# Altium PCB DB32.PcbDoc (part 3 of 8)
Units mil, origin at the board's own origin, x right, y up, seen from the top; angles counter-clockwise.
Board outline 3236.22 x 4456.69 mil, 8 copper layers (Top Layer, MidLayer1, MidLayer2, GND-Layer5, MidLayer3, VCC, MidLayer4, Bottom Layer), stack 61.8 mil thick; 207 components, 474 nets, 1777 pads, 1474 vias.
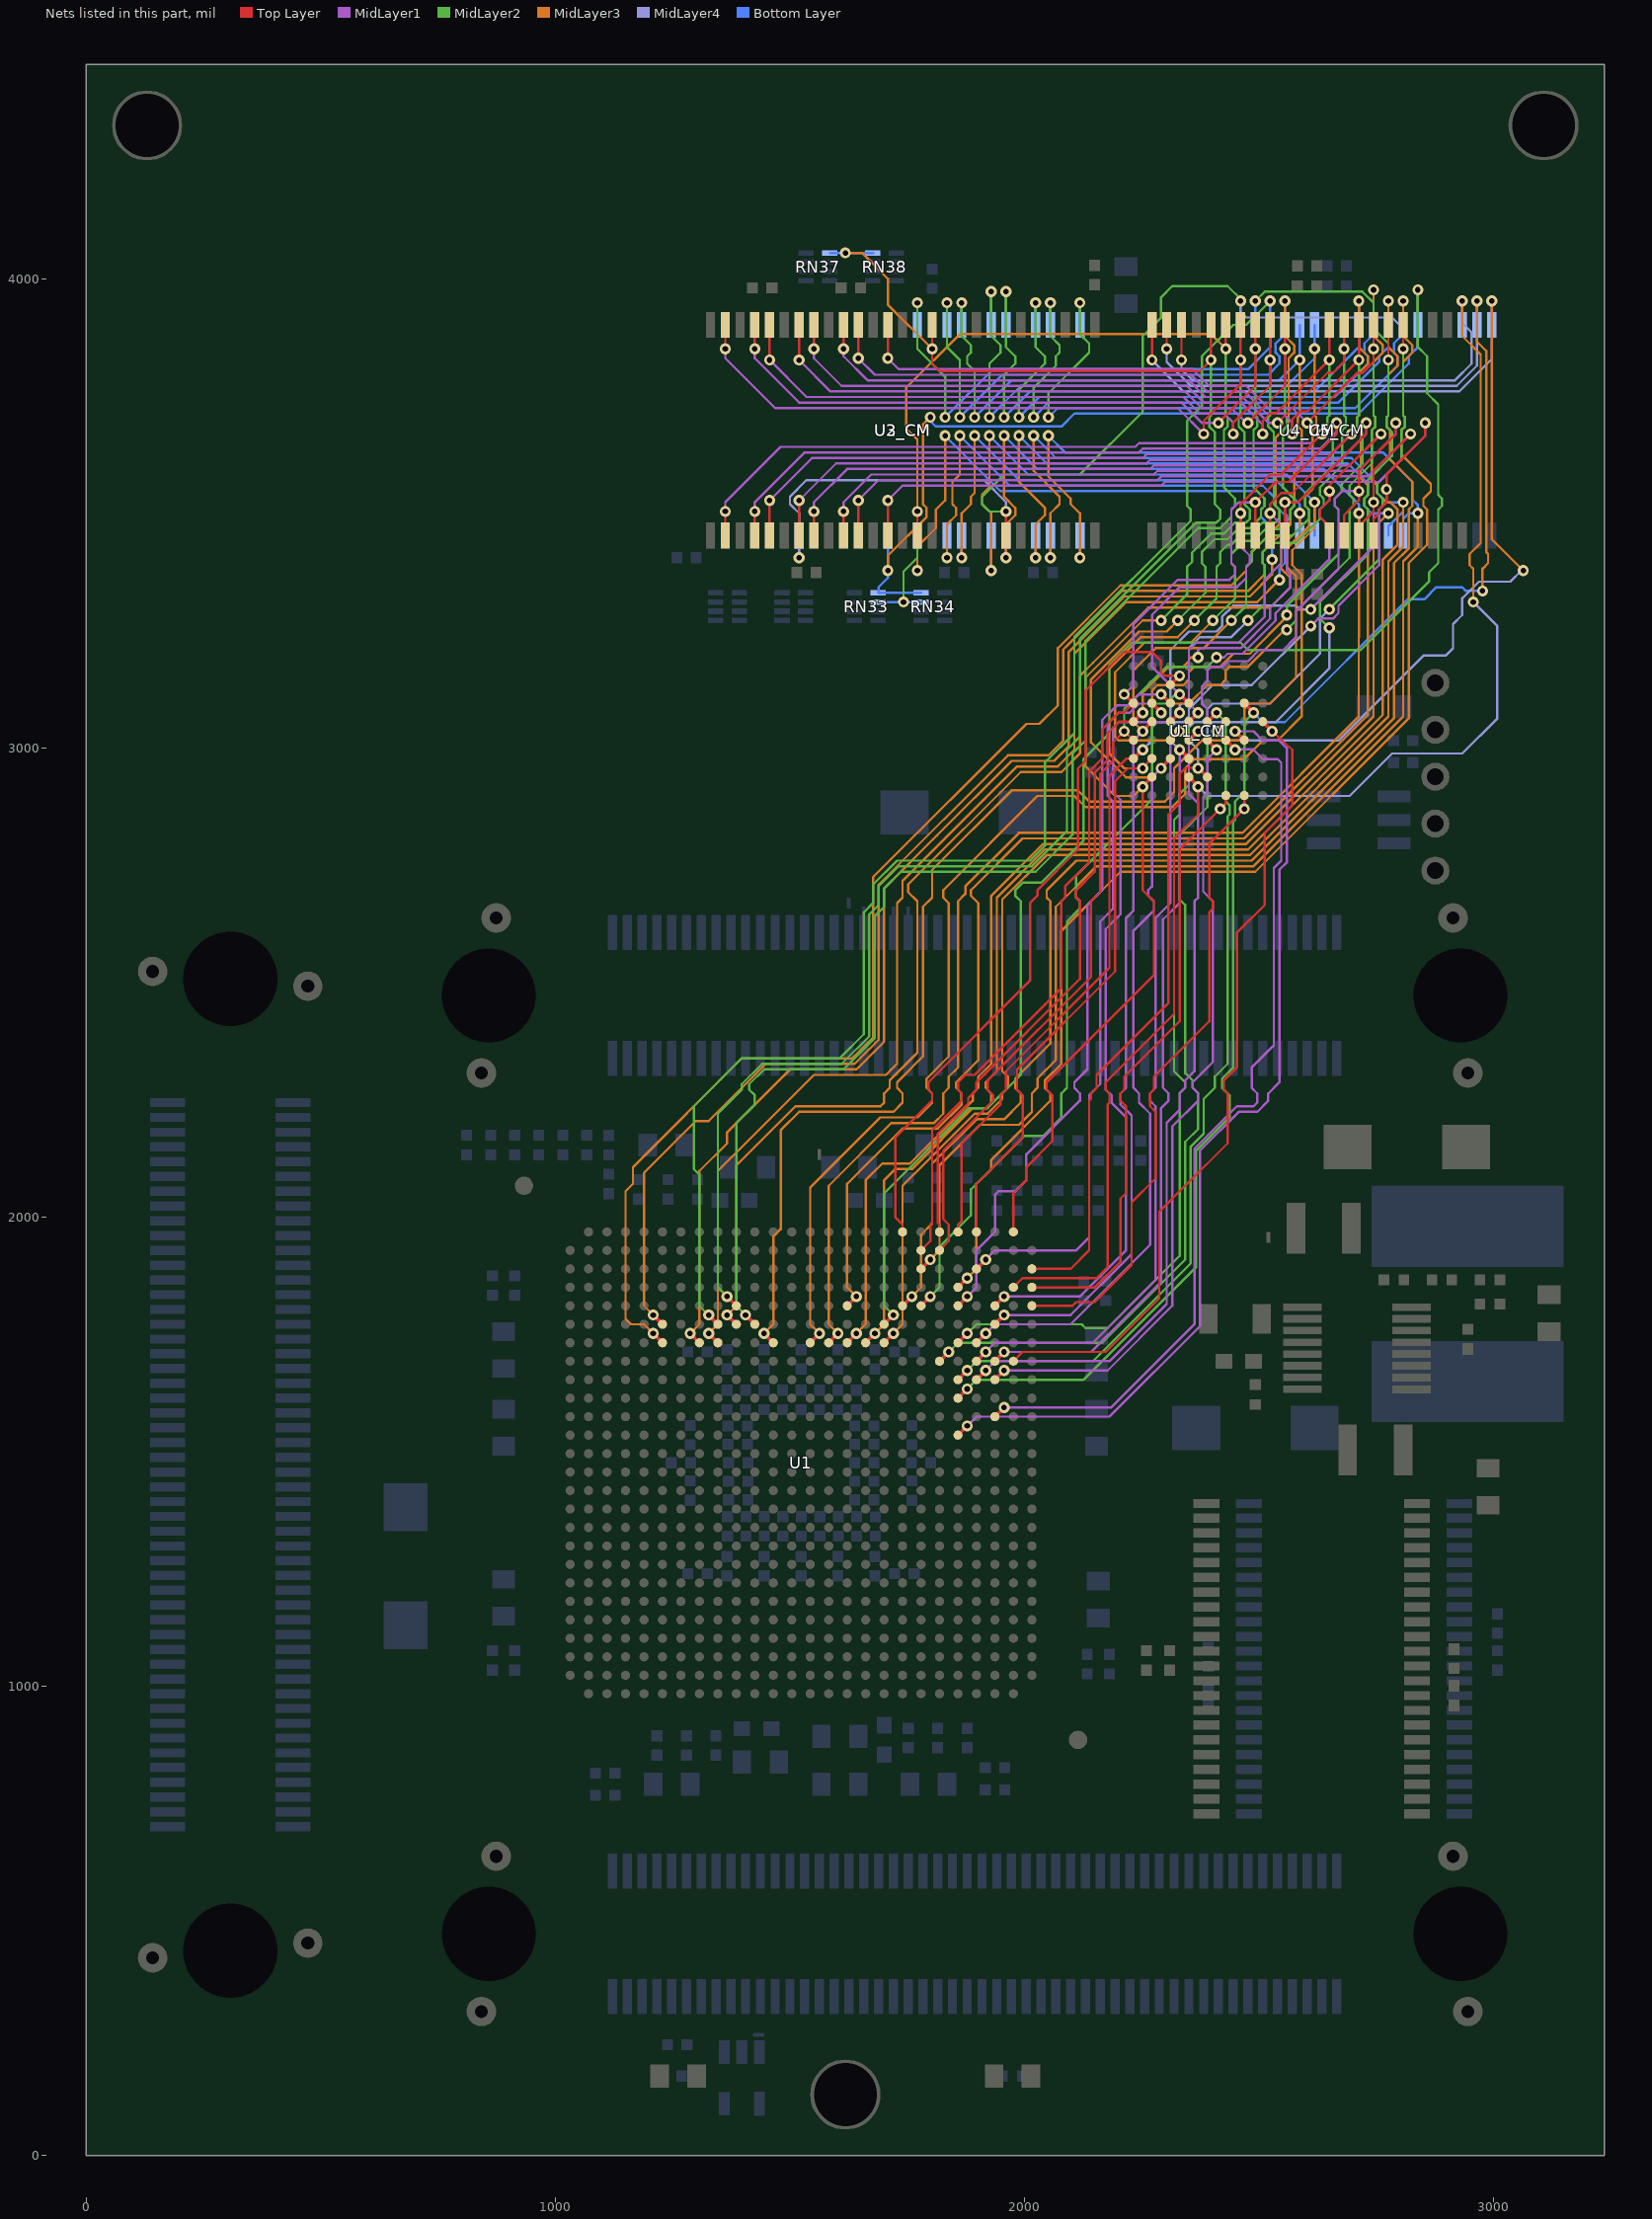
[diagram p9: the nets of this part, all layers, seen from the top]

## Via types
v1: diameter 23.62, hole 11.81, Top Layer to Bottom Layer, 839 vias
v2: diameter 23.62, hole 11.81, Top Layer to Bottom Layer, tented both sides, 499 vias
v3: diameter 27.56, hole 15.75, Top Layer to Bottom Layer, 135 vias
v4: diameter 23.62, hole 11.81, Top Layer to Bottom Layer, tented top, 1 vias

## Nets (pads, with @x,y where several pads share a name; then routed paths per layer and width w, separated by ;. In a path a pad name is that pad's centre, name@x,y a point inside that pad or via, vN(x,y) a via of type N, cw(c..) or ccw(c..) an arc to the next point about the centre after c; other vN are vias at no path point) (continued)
BUS_A16: U1.C26 U1_CM.D7 U2_CM.21 U3_CM.21 U4_CM.27 U5_CM.27 | length 4718.6
  Top Layer w5: U2_CM.21@1960.63,3452.76 v2(1960.63,3503.93) ; U1.C26@2015.75,1889.76 2078.74,1889.76 2090.55,1889.76 2098.43,1889.76 2137.8,1929.13 2137.8,2248.03 2141.73,2251.97 2141.73,2263.78 2153.54,2275.59 2153.54,2303.15 2307.09,2456.69 2307.09,2858.27 2330.71,2881.89 2330.71,2944.88 2343.51,2957.68 v1@2370.08,2957.68 ; v2(2807.09,3850.39) U4_CM.27@2807.09,3901.57
  Top Layer w7.87: v1@2370.08,2957.68 2370.57,2957.19 U1_CM.D7@2389.76,2937.99
  MidLayer2 w5: v2(1960.63,3503.93) 1925.2,3503.93 1909.45,3519.68 1909.45,3535.43 1925.2,3551.18 1956.69,3582.68 2118.11,3582.68 2251.97,3716.54 2251.97,3877.95 2291.34,3917.32 2291.34,3960.63 2314.96,3984.25 2433.07,3984.25 2460.63,3956.69 v2(2460.63,3952.76) ; v1(2649.61,3295.28) 2755.91,3401.57 2755.91,3507.87 2763.78,3515.75 2763.78,3531.5 2751.97,3543.31 2751.97,3562.99 2803.15,3614.17 2803.15,3677.17 2811.02,3685.04 2811.02,3704.72 2807.09,3708.66 v2(2807.09,3850.39)
  MidLayer4 w5: v2(1519.68,3405.51) 1519.68,3500 1500,3519.68 1500,3535.43 1535.43,3570.87 1913.38,3570.87 1960.63,3523.63 v2(1960.63,3503.93) ; v1(2370.08,2956.69) 2370.08,2996.06 2350.39,3015.75 2350.39,3043.31 2362.2,3055.12 2377.95,3055.12 2389.76,3066.93 2389.76,3082.68 2401.57,3094.49 2523.62,3094.49 2629.92,3200.79 2629.92,3275.59 v1(2649.61,3295.28) ; v2(2460.63,3952.76) 2460.63,3929.13 2472.44,3917.32 2783.46,3917.32 2807.09,3893.7 v2(2807.09,3850.39)
  Bottom Layer w5: v2(1519.68,3405.51) U3_CM.21@1519.68,3452.76 ; U5_CM.27@2460.63,3901.57 v2(2460.63,3952.76)
BUS_A17: U1.D25 U1_CM.E7 U4_CM.42 U5_CM.42 | length 3942.3
  Top Layer w5: U1.D25@1976.38,1850.39 1996.06,1870.08 2078.74,1870.08 2090.55,1870.08 2153.54,1870.08 2177.17,1893.7 2177.17,2240.16 2181.1,2244.09 2181.1,2263.78 2173.23,2271.65 2173.23,2287.4 2318.9,2433.07 2318.9,2807.09 2370.08,2858.27 v1(2370.08,2917.32) ; v2(2334.64,3826.77) U4_CM.42@2334.64,3901.57
  Top Layer w7.87: U1_CM.E7@2350.39,2937.99 v1(2370.08,2917.32)
  MidLayer3 w5: v2(2933.07,3952.76) 2933.07,3877.95 2972.44,3838.58 2972.44,3437.01 2948.82,3413.39 2948.82,3389.76 2956.69,3381.89 v1(2956.69,3311.02)
  MidLayer4 w5: v2(2334.64,3826.77) 2334.64,3807.09 2358.27,3783.46 2917.32,3783.46 2952.76,3818.9 2952.76,3885.83 2933.07,3905.51 v2(2933.07,3952.76) ; v1(2370.08,2917.32) 2389.76,2897.64 2692.91,2897.64 2783.46,2988.19 2933.07,2988.19 3007.87,3062.99 3007.87,3259.84 v1(2956.69,3311.02)
  Bottom Layer w5: U5_CM.42@2933.07,3901.57 v2(2933.07,3952.76)
BUS_A18: U1.K22 U1_CM.B3 U4_CM.43 U5_CM.43 | length 4116.9
  Top Layer w5: v2(2303.15,3850.39) U4_CM.43@2303.15,3901.57 ; v1(2488.19,3074.8) v1@2488.19,3075.79
  Top Layer w7.87: U1.K22@1858.27,1614.17 v1(1877.96,1633.86) ; U1_CM.B3@2468.5,3095.47 v1@2488.19,3075.79
  MidLayer2 w5: v1(1877.96,1633.86) 1897.64,1653.54 2078.74,1653.54 2090.55,1653.54 2125.98,1653.54 2366.14,1893.7 2366.14,2141.73 2437.01,2212.6 2437.01,2259.84 2421.26,2275.59 2421.26,2295.28 2444.88,2318.9 2444.88,2673.23 2444.88,2842.52 2448.82,2846.46 2448.82,2885.83 2468.5,2905.51 2468.5,2976.38 2468.5,3055.12 v1(2488.19,3074.8)
  MidLayer3 w5: v2(2964.57,3952.76) 2964.57,3866.14 2984.25,3846.46 2984.25,3417.32 2988.19,3413.39 2988.19,3393.7 2976.38,3381.89 v1(2976.38,3334.65)
  MidLayer4 w5: v2(2303.15,3850.39) 2303.15,3822.83 2354.33,3771.65 2921.26,3771.65 2964.57,3814.96 v2(2964.57,3952.76)
  Bottom Layer w5: v1(2488.19,3074.8) 2507.87,3055.12 2555.12,3055.12 2816.68,3316.68 2852.11,3316.68 2877.95,3342.52 2933.07,3342.52 2940.94,3334.65 v1(2976.38,3334.65) ; U5_CM.43@2964.57,3901.57 v2(2964.57,3952.76)
BUS_A19: U1.H21 U1_CM.C4 U4_CM.44 U5_CM.44 | length 4323.6
  Top Layer w5: v2(2271.65,3826.77) U4_CM.44@2271.65,3901.57
  Top Layer w7.87: U1.H21@1818.9,1692.91 v1(1838.59,1712.6) ; v1(2409.45,3035.43) U1_CM.C4@2429.13,3056.1
  MidLayer2 w5: v1(1838.59,1712.6) 1858.27,1732.28 2078.74,1732.28 2090.55,1732.28 2165.35,1732.28 2342.52,1909.45 2342.52,2160.43 2370.08,2187.99 2370.08,2263.78 2358.27,2275.59 2358.27,2291.34 2342.52,2307.09 2342.52,2665.35 2330.71,2677.17 2330.71,2814.96 2389.76,2874.02 2389.76,3015.75 v1(2409.45,3035.43)
  MidLayer3 w5: v2(2996.06,3952.76) 2996.06,3633.86 2996.06,3444.88 v1(3062.99,3377.95)
  MidLayer4 w5: v2(2271.65,3826.77) 2338.58,3759.84 2926.67,3759.84 2996.06,3829.23 v2(2996.06,3952.76) ; v1(2409.45,3035.43) 2429.13,3015.75 2669.29,3015.75 2850.39,3196.85 2897.64,3196.85 2913.39,3212.6 2913.39,3263.78 2933.07,3283.46 2933.07,3318.9 2968.5,3354.33 3035.43,3354.33 3059.06,3377.95 v1(3062.99,3377.95)
  Bottom Layer w5: U5_CM.44@2996.06,3901.57 v2(2996.06,3952.76)
BUS_A20: U1.J24 U1_CM.D5 U4_CM.28 U5_CM.28 | length 3363.5
  Top Layer w5: v2(2775.59,3826.77) U4_CM.28@2775.59,3901.57
  Top Layer w7.87: U1.J24@1937.01,1653.54 v1(1956.7,1673.23) ; U1_CM.D5@2389.76,3016.73 v1(2409.45,2996.06)
  MidLayer1 w5: v1(1956.7,1673.23) 2078.74,1673.23 2090.55,1673.23 2177.17,1673.23 2314.96,1811.02 2314.96,2192.91 2370.08,2248.03 2370.08,2263.78 2358.27,2275.59 2358.27,2287.4 2401.57,2330.71 2401.57,2673.23 2380.91,2693.9 2380.91,2894.69 2389.76,2903.54 2389.76,2976.38 v1(2409.45,2996.06)
  MidLayer2 w5: v2(2492.13,3952.76) 2511.81,3972.44 2720.47,3972.44 2744.09,3948.82 2744.09,3893.7 2775.59,3862.21 v2(2775.59,3826.77) 2775.59,3708.66 2771.65,3704.72 2771.65,3685.04 2783.46,3673.23 2783.46,3622.05 2732.28,3570.87 2732.28,3539.37 2724.41,3531.5 2724.41,3515.75 2732.28,3507.87 2732.28,3413.39 2629.92,3311.02 2629.92,3275.59 v1(2649.61,3255.91)
  MidLayer4 w5: v1(2409.45,2996.06) 2389.76,3015.75 2389.76,3043.31 2401.57,3055.12 2535.43,3055.12 2649.61,3169.29 v1(2649.61,3255.91)
  Bottom Layer w5: U5_CM.28@2492.13,3901.57 v2(2492.13,3952.76)
BUS_A21: U1.J22 U1_CM.D4 | length 1844.8
  Top Layer w7.87: U1.J22@1858.27,1653.54 v1(1877.96,1673.23) ; U1_CM.D4@2389.76,3056.1 v1(2409.45,3074.8)
  MidLayer2 w5: v1(1877.96,1673.23) 1897.64,1692.91 2078.74,1692.91 2090.55,1692.91 2145.67,1692.91 2354.33,1901.57 2354.33,2150.59 2381.89,2178.15 2381.89,2251.97 2405.51,2275.59 2405.51,2299.21 2433.07,2326.77 2433.07,2749.01 2433.07,2854.33 2437.01,2858.27 2437.01,2877.95 2429.13,2885.83 2429.13,2909.45 2429.13,3055.12 v1(2409.45,3074.8)
BUS_A22: U1.L24 U1_CM.C5 | length 1949.8
  Top Layer w7.87: U1.L24@1937.01,1574.8 v1(1956.7,1594.49) ; U1_CM.C5@2429.13,3016.73 v1@2448.82,2997.05
  MidLayer1 w5: v1(1956.7,1594.49) 2078.74,1594.49 2090.55,1594.49 2185.04,1594.49 2362.2,1771.65 2362.2,2145.67 2452.76,2236.22 2488.19,2236.22 2496.06,2244.09 2496.06,2263.78 2484.25,2275.59 2484.25,2318.9 2531.5,2366.14 2531.5,2744.09 2547.24,2759.84 2547.24,2968.5 2539.37,2976.38 2507.87,2976.38 2487.2,2997.05 v1@2448.82,2997.05
  Bottom Layer w5: v1@2447.83,2997.05 v1@2448.82,2997.05
  other v1: 2448.82,2996.06
BUS_A23: U1.E26 U1_CM.B8 | length 1380.3
  Top Layer w5: U1.E26@2015.75,1811.02 2078.74,1811.02 2090.55,1811.02 2102.36,1811.02 2110.24,1818.9 2149.6,1818.9 2228.35,1897.64 2228.35,2031.5 2279.53,2082.68 2279.53,2224.41 2267.72,2236.22 2267.72,2263.78 2275.59,2271.65 2275.59,2299.21 2393.7,2417.32 2393.7,2649.61 2401.57,2657.48 2401.57,2673.23 2393.7,2681.1 2393.7,2731.56 ; 2393.7,2716.54 2393.7,2795.28 v1(2468.51,2870.08) U1_CM.B8@2468.5,2898.62
BUS_A24: U1.D26 U1_CM.C8 | length 1307.7
  Top Layer w5: U1.D26@2015.75,1850.39 2078.74,1850.39 2090.55,1850.39 2149.61,1850.39 2204.72,1905.51 2204.72,2039.37 2216.54,2051.18 2216.54,2236.22 2204.72,2248.03 2204.72,2263.78 2212.6,2271.65 2212.6,2299.21 2330.71,2417.32 2330.71,2783.46 v1(2417.32,2870.08) 2429.14,2881.89 U1_CM.C8@2429.13,2898.62
BUS_D0: U1.E20 U1_CM.E3 U2_CM.2 U4_CM.7 | length 3888
  Top Layer w5: U2_CM.2@1362.2,3452.76 v2(1362.2,3503.93) ; U4_CM.7@2460.63,3452.76 v1(2460.63,3500) 2460.63,3519.69 2523.62,3582.68 2547.24,3582.68 v2(2633.86,3669.29)
  Top Layer w7.87: U1.E20@1779.53,1811.02 v1(1799.21,1830.71) ; v1(2330.71,3114.17) U1_CM.E3@2350.4,3095.48
  MidLayer1 w5: v2(1362.2,3503.93) 1362.2,3523.62 1480.31,3641.73 2236.22,3641.73 2244.09,3649.61 2614.17,3649.61 v2(2633.86,3669.29) ; v1(2330.71,3114.17) 2271.65,3173.23 2271.65,3283.46 2330.71,3342.52 2452.76,3342.52 2472.44,3362.2 2472.44,3385.83 2480.31,3393.7 2480.31,3409.45 2460.63,3429.13 v1(2460.63,3500)
  MidLayer2 w5: v1(1799.21,1830.71) 1818.9,1850.39 1818.9,1937.01 1885.83,2003.94 1885.83,2031.5 1885.83,2043.31 1885.83,2059.06 2000,2173.23 2039.37,2173.23 2078.74,2212.6 2078.74,2263.78 2090.55,2275.59 2090.55,2629.92 2118.11,2657.48 2118.11,2673.23 2110.24,2681.1 2110.24,2728.35 2271.65,2889.76 2271.65,3086.61 2279.53,3094.49 2302.17,3094.49 2321.85,3114.17 v1(2330.71,3114.17)
BUS_D1: U1.B20 U1_CM.H3 U2_CM.4 U4_CM.8 | length 3743.3
  Top Layer w5: U2_CM.4@1425.2,3452.76 v2(1425.19,3503.93) ; U1.B20@1779.53,1929.13 1799.21,1948.82 1799.21,1984.25 1803.15,1988.19 1803.15,2031.5 1803.15,2043.31 1803.15,2185.04 1866.14,2248.03 1866.14,2263.78 1858.27,2271.65 1858.27,2287.4 1874.02,2303.15 1893.7,2303.15 2078.74,2488.19 2078.74,2673.23 2086.61,2681.1 2086.61,2704.73 2137.8,2755.91 2137.8,2949.54 2165.35,2977.1 2165.35,3039.37 2201.28,3075.3 2212.1,3075.3 U1_CM.H3@2232.29,3095.48 ; U4_CM.8@2492.13,3452.76 v1(2492.13,3523.62) 2535.43,3566.93 2562.99,3566.93 2665.35,3669.29 v2(2665.35,3692.91)
  Top Layer w7.87: v1(2212.6,3114.17) U1_CM.H3@2232.29,3095.48
  MidLayer1 w5: v2(1425.19,3503.93) 1425.19,3523.62 1531.5,3629.92 2244.09,3629.92 2251.97,3637.8 2629.92,3637.8 2665.35,3673.23 v2(2665.35,3692.91) ; v1(2212.6,3114.17) 2232.28,3133.86 2232.28,3263.78 2326.77,3358.27 2437.01,3358.27 2448.82,3370.08 2448.82,3385.83 2440.94,3393.7 2440.94,3507.87 2456.69,3523.62 v1(2492.13,3523.62)
BUS_D2: U1.G22 U1_CM.E4 U2_CM.5 U4_CM.9 | length 4029.6
  Top Layer w5: U2_CM.5@1456.69,3452.76 v2(1456.69,3527.55) ; U4_CM.9@2523.62,3452.76 v1(2523.62,3500) 2523.62,3519.69 2547.24,3543.31 2570.87,3543.31 v2(2696.85,3669.29)
  Top Layer w7.87: U1.G22@1858.27,1732.28 v1(1877.95,1751.97) ; U1_CM.E4@2350.39,3056.1 v1(2370.08,3074.81)
  MidLayer1 w5: v2(1456.69,3527.55) 1547.24,3618.11 2251.97,3618.11 2259.84,3625.98 2653.54,3625.98 v2(2696.85,3669.29) ; v1(2370.08,3074.81) 2350.39,3094.5 2350.39,3208.66 2366.14,3224.41 2456.69,3224.41 2511.81,3279.53 2511.81,3358.27 2547.24,3393.7 2547.24,3476.38 v1(2523.62,3500)
  MidLayer2 w5: v1(1877.95,1751.97) 1897.64,1771.65 2078.74,1771.65 2090.55,1771.65 2122.05,1771.65 2129.92,1763.78 2177.17,1763.78 2330.71,1917.32 2330.71,2263.78 2342.52,2275.59 2342.52,2287.4 2318.9,2311.02 2318.9,2846.46 2330.71,2858.27 2330.71,2901.57 2350.39,2921.26 2350.39,3055.12 v1(2370.08,3074.81)
BUS_D3: U1.A21 U1_CM.H4 U2_CM.7 U4_CM.10 | length 3670.1
  Top Layer w5: U2_CM.7@1519.69,3452.76 v2(1519.68,3527.56) ; U1.A21@1818.9,1968.5 1818.9,1984.25 1814.96,1988.19 1814.96,2031.5 1814.96,2043.31 1814.96,2177.17 1879.92,2242.13 1879.92,2253.94 1897.64,2271.65 1897.64,2287.4 2118.11,2507.87 2118.11,2673.23 2110.24,2681.1 2110.24,2696.85 2149.61,2736.22 2149.61,2947.21 2177.17,2974.77 2177.17,3031.5 2201.78,3056.11 U1_CM.H4@2232.28,3056.1 ; U4_CM.10@2555.12,3452.76 v1(2555.12,3523.62) 2582.68,3523.62 2640.75,3581.69 2728.35,3669.29 v2(2728.35,3692.91)
  Top Layer w7.87: U1_CM.H4@2232.28,3056.1 v1@2251.47,3075.3
  MidLayer1 w5: v2(1519.68,3527.56) 1598.43,3606.3 2259.84,3606.3 2267.72,3614.17 2673.23,3614.17 2728.35,3669.29 v2(2728.35,3692.91) ; v1(2370.08,3192.91) 2370.08,3208.66 2374.02,3212.6 2460.63,3212.6 2523.62,3275.59 2523.62,3299.21 2566.93,3342.52 2566.93,3370.08 2559.06,3377.95 2559.06,3496.06 2555.12,3500 v1(2555.12,3523.62)
  MidLayer3 w5: v1(2251.97,3074.8) 2251.97,3118.11 2255.91,3122.05 2307.09,3173.23 2338.58,3173.23 2350.39,3185.04 2350.39,3188.98 2354.33,3192.91 v1(2370.08,3192.91)
BUS_D4: U1.B21 U1_CM.H5 U2_CM.8 U4_CM.13 | length 3722
  Top Layer w5: U2_CM.8@1551.18,3452.76 v2(1551.18,3503.94) ; U1.B21@1818.9,1929.13 1838.58,1948.82 1838.58,1984.25 1826.77,1996.06 1826.77,2031.5 1826.77,2043.31 1826.77,2141.73 1933.07,2248.03 1933.07,2259.84 1921.26,2271.65 1921.26,2291.34 2141.73,2511.81 2141.73,2673.23 2161.42,2692.91 2161.42,2944.88 2188.98,2972.44 2188.98,3011.81 v1(2212.6,3035.43) U1_CM.H5@2232.28,3016.73 ; U4_CM.13@2649.61,3452.76 2649.61,3472.44 2629.92,3492.13 2629.92,3507.87 2649.61,3527.56 v1(2649.61,3547.24) 2649.61,3559.06 v2(2759.84,3669.29)
  MidLayer1 w5: v2(1551.18,3503.94) 1551.18,3523.62 1622.05,3594.49 2267.72,3594.49 2275.59,3602.36 2692.91,3602.36 v2(2759.84,3669.29) ; v1(2409.45,3192.91) 2425.2,3192.91 2433.07,3200.79 2464.57,3200.79 2535.43,3271.65 2535.43,3287.4 2649.61,3401.57 2649.61,3472.44 2629.92,3492.13 2629.92,3507.87 2649.61,3527.56 v1(2649.61,3547.24)
  MidLayer2 w5: v1(2212.6,3035.43) 2212.6,3082.68 2303.15,3173.23 2389.76,3173.23 v1(2409.45,3192.91)
BUS_D5: U1.J23 U1_CM.E5 U2_CM.10 U4_CM.14 | length 4157.5
  Top Layer w5: U2_CM.10@1614.17,3452.76 v2(1614.17,3503.93) ; U4_CM.14@2681.1,3452.76 2681.1,3496.06 2712.6,3527.56 v1(2712.6,3547.24) 2712.6,3590.55 2791.34,3669.29 v2(2791.34,3692.91)
  Top Layer w7.87: U1.J23@1897.64,1653.54 v1(1917.33,1673.23) ; U1_CM.E5@2350.39,3016.73 v1(2370.08,3035.43)
  MidLayer1 w5: v2(1614.17,3503.93) 1614.17,3523.62 1673.23,3582.68 2275.59,3582.68 2283.46,3590.55 2712.6,3590.55 2791.34,3669.29 v2(2791.34,3692.91) ; v1(1917.33,1673.23) 1937.01,1692.91 2078.74,1692.91 2090.55,1692.91 2181.1,1692.91 2303.15,1814.96 2303.15,2200.79 2330.71,2228.35 2330.71,2263.78 2342.52,2275.59 2342.52,2291.34 2362.2,2311.02 2362.2,2673.23 2370.08,2681.1 2370.08,2720.47 ; 2370.08,2704.72 2370.08,2720.47 ; v1(2712.6,3547.24) 2677.17,3547.24 2661.42,3531.5 2661.42,3515.75 2669.29,3507.87 2669.29,3381.89 2578.74,3291.34 2578.74,3236.22 2551.18,3208.66 2500,3208.66 2476.38,3185.04 2433.07,3185.04 2421.26,3173.23 2397.64,3173.23 2389.76,3165.35 2389.76,3141.73 2377.95,3129.92 2377.95,3094.49 2389.76,3082.68 2389.76,3055.12 v1(2370.08,3035.43) 2350.39,3015.75 2350.39,2901.57 2370.08,2881.89 2370.08,2720.47
BUS_D6: U1.A22 U1_CM.H6 U2_CM.11 U4_CM.15 | length 3658.7
  Top Layer w5: U2_CM.11@1645.67,3452.76 v2(1645.66,3527.55) ; U1.A22@1858.27,1968.5 1858.27,1984.25 1866.14,1992.13 1866.14,2031.5 1866.14,2043.31 1866.14,2157.48 1948.82,2240.16 1948.82,2259.84 1960.63,2271.65 1960.63,2311.02 2181.1,2531.5 2181.1,2940.94 2217.52,2977.37 U1_CM.H6@2232.28,2977.36 ; U4_CM.15@2712.6,3452.76 2712.6,3472.44 2744.09,3503.94 v1(2744.09,3523.62) 2744.09,3590.55 v2(2822.83,3669.29)
  Top Layer w7.87: U1_CM.H6@2232.28,2977.36 2251.47,2996.56 v1@2251.97,2997.05
  MidLayer1 w5: v2(1645.66,3527.55) 1688.98,3570.87 2283.46,3570.87 2291.34,3578.74 2732.28,3578.74 v2(2822.83,3669.29) ; v1(2610.24,3295.28) 2744.09,3429.13 v1(2744.09,3523.62)
  MidLayer4 w5: v1(2251.97,2996.06) 2271.65,3015.75 2271.65,3043.31 2283.46,3055.12 2303.15,3055.12 2311.02,3062.99 2311.02,3208.66 2350.39,3248.03 2409.45,3248.03 2421.26,3259.84 2421.26,3279.53 2444.88,3303.15 2578.74,3303.15 2586.61,3295.28 v1(2610.24,3295.28)
BUS_D7: U1.H24 U1_CM.E6 U2_CM.13 U4_CM.16 | length 4054
  Top Layer w5: U2_CM.13@1708.66,3452.76 v2(1708.66,3527.55) ; U4_CM.16@2744.09,3452.76 2744.09,3488.19 2755.91,3500 2755.91,3507.87 2771.65,3523.62 v1(2771.65,3551.18) 2771.65,3582.68 2854.33,3665.35 v2(2854.33,3692.91)
  Top Layer w7.87: U1.H24@1937.01,1692.91 v1(1956.7,1712.6) ; v1@2330.71,2997.05 2331.2,2996.56 U1_CM.E6@2350.39,2977.36
  MidLayer1 w5: v2(1708.66,3527.55) 1740.16,3559.06 2291.34,3559.06 2299.21,3566.93 2755.91,3566.93 2854.33,3665.35 v2(2854.33,3692.91) ; v1(1956.7,1712.6) 2078.74,1712.6 2090.55,1712.6 2141.73,1712.6 2291.34,1862.2 2291.34,2232.28 2307.09,2248.03 2307.09,2263.78 2295.28,2275.59 2295.27,2633.86 2330.71,2669.29 2330.71,2700.79 ; 2330.71,2681.1 v1(2330.71,2996.06) v1@2330.71,2997.05 ; v1(2610.24,3259.84) 2625.98,3275.59 2657.48,3275.59 2669.29,3287.4 2669.29,3303.15 2755.91,3389.76 2755.91,3507.87 2771.65,3523.62 v1(2771.65,3551.18)
  MidLayer4 w5: v1(2330.71,2996.06) 2311.02,3015.75 2311.02,3043.31 2322.83,3055.12 2338.58,3055.12 2350.39,3066.93 2350.39,3082.68 2401.57,3133.86 2484.25,3133.86 v1(2610.24,3259.84)
BUS_D8: U1.E22 U1_CM.F3 U2_CM.42 U4_CM.29 | length 3915.8
  Top Layer w5: v2(1708.66,3830.71) U2_CM.42@1708.66,3901.57 ; v2(2602.36,3692.91) 2708.17,3798.72 2719.98,3798.72 2744.09,3822.83 v2(2744.09,3850.39) U4_CM.29@2744.09,3901.57
  Top Layer w7.87: U1.E22@1858.27,1811.02 v1(1877.95,1830.71) ; v1@2291.34,3115.16 2291.83,3114.67 U1_CM.F3@2311.03,3095.48
  MidLayer1 w5: v2(1708.66,3830.71) 1732.28,3807.09 2358.27,3807.09 2393.7,3771.65 2472.44,3771.65 2519.69,3724.41 2570.87,3724.41 v2(2602.36,3692.91) ; v1(1877.95,1830.71) 1897.64,1850.39 1897.64,1929.13 1937.01,1968.5 1937.01,2031.5 1937.01,2043.31 1937.01,2047.24 1944.88,2055.12 1980.31,2055.12 2003.94,2078.74 2003.94,2133.86 2118.11,2248.03 2118.11,2263.78 2106.3,2275.59 2106.3,2287.4 2133.86,2314.96 2133.86,2665.35 2165.35,2696.85 2165.35,3059.06 2196.85,3090.55 2220.47,3090.55 2244.09,3114.17 v1(2291.34,3114.17)
  MidLayer2 w5: v1(2559.06,3251.97) 2578.74,3271.65 2578.74,3291.34 2692.91,3405.51 2692.91,3507.87 2700.79,3515.75 2700.79,3531.5 2692.91,3539.37 2692.91,3559.06 2740.16,3606.3 2740.16,3677.17 2748.03,3685.04 2748.03,3704.72 2744.09,3708.66 v2(2744.09,3850.39)
  MidLayer3 w5: v1(2291.34,3114.17) 2311.02,3094.49 2350.39,3094.49 2389.76,3133.86 2417.32,3133.86 2429.13,3145.67 2429.13,3165.35 2437.01,3173.23 2476.38,3173.23 2555.12,3251.97 v1(2559.06,3251.97)
BUS_D9: U1.C23 U1_CM.G3 U2_CM.44 U4_CM.30 | length 4002.3
  Top Layer w5: v2(1645.67,3830.71) U2_CM.44@1645.67,3901.57 ; v2(2570.87,3669.29) 2570.87,3700.79 2586.61,3716.54 2602.36,3716.54 v2(2712.6,3826.77) U4_CM.30@2712.6,3901.57
  Top Layer w7.87: U1.C23@1897.64,1889.76 v1(1917.32,1909.45) ; U1_CM.G3@2271.65,3095.48 v1(2291.34,3074.8)
  MidLayer1 w5: v2(1645.67,3830.71) 1681.1,3795.28 2354.33,3795.28 2389.76,3759.84 2469,3759.84 2516.24,3712.6 2551.18,3712.6 2570.87,3692.91 v2(2570.87,3669.29) ; v1(1917.32,1909.45) 1937.01,1929.13 2078.74,1929.13 2090.55,1929.13 2110.24,1929.13 2137.8,1956.69 2137.8,2259.84 2161.42,2283.46 2161.42,2629.92 2188.98,2657.48 2188.98,2724.41 ; 2188.98,2700.79 2188.98,2885.83 2177.17,2897.64 2177.17,3051.18 2200.79,3074.8 2224.41,3074.8 2244.09,3094.49 2271.65,3094.49 v1(2291.34,3074.8)
  MidLayer2 w5: v1(2559.06,3283.46) 2559.06,3303.15 2669.29,3413.39 2669.29,3507.87 2661.42,3515.75 2661.42,3531.5 2676.18,3546.26 2676.18,3562.01 2720.47,3606.3 2720.47,3673.23 2708.66,3685.04 2708.66,3704.72 2712.6,3708.66 v2(2712.6,3826.77)
  MidLayer3 w5: v1(2291.34,3074.8) 2271.65,3094.49 2271.65,3122.05 2283.46,3133.86 2338.58,3133.86 2350.39,3145.67 2350.39,3161.42 2362.2,3173.23 2417.32,3173.23 2444.88,3200.79 2480.31,3200.79 2559.06,3279.53 v1(2559.06,3283.46)
BUS_D10: U1.E24 U1_CM.F4 U2_CM.45 U4_CM.31 | length 3995.9
  Top Layer w5: v2(1614.17,3850.39) U2_CM.45@1614.17,3901.57 ; v2@2537.4,3694.88 2539.37,3694.88 2541.34,3694.88 2646.65,3800.2 2658.46,3800.2 2681.1,3822.83 v2(2681.1,3850.39) U4_CM.31@2681.1,3901.57
  Top Layer w7.87: U1.E24@1937.01,1811.02 v1(1956.69,1830.71) ; U1_CM.F4@2311.02,3056.1 v1(2330.71,3074.8)
  MidLayer1 w5: v2(1614.17,3850.39) 1614.17,3834.65 1665.35,3783.46 2350.39,3783.46 2385.83,3748.03 2464.57,3748.03 2519.69,3692.91 v2(2539.37,3692.91) ; v1(1956.69,1830.71) 2078.74,1830.71 2090.55,1830.71 2118.11,1830.71 2216.54,1929.13 2216.54,2212.6 2186.02,2243.11 2186.02,2258.86 2173.23,2271.65 2173.23,2614.17 2204.72,2645.67 2204.72,2889.76 2188.98,2905.51 2188.98,3043.31 2200.79,3055.12 2311.02,3055.12 v1(2330.71,3074.8)
  MidLayer2 w5: v1(2476.38,3271.65) 2511.81,3307.09 2511.81,3389.76 2507.87,3393.7 2507.87,3417.32 2527.56,3437.01 2578.74,3437.01 2629.92,3488.19 2629.92,3507.87 2637.8,3515.75 2637.8,3531.5 2629.92,3539.37 2629.92,3555.12 2677.16,3602.36 2677.16,3677.17 2685.04,3685.04 2685.04,3704.72 2681.1,3708.66 v2(2681.1,3850.39)
  MidLayer4 w5: v1(2330.71,3074.8) 2330.71,3090.55 2334.65,3094.49 2342.52,3094.49 2350.39,3102.36 2350.39,3212.6 2374.02,3236.22 2440.94,3236.22 v1(2476.38,3271.65)
BUS_D11: U1.F24 U1_CM.G4 U2_CM.47 U4_CM.32 | length 4007.9
  Top Layer w5: v2(1551.18,3850.39) U2_CM.47@1551.18,3901.57 ; v2(2507.87,3669.29) 2507.87,3696.85 2523.62,3712.6 2535.43,3712.6 v2(2649.61,3826.77) U4_CM.32@2649.61,3901.57
  Top Layer w7.87: U1.F24@1937.01,1771.65 v1(1956.7,1791.34) ; v1(2251.97,3035.43) U1_CM.G4@2271.65,3056.1
  MidLayer1 w5: v2(1551.18,3850.39) 1551.18,3830.71 1610.24,3771.65 2346.46,3771.65 2381.89,3736.22 2460.63,3736.22 2507.87,3688.98 v2(2507.87,3669.29) ; v1(1956.7,1791.34) 2078.74,1791.34 2090.55,1791.34 2098.43,1791.34 2228.35,1921.26 2228.35,2216.54 2204.68,2240.21 2204.68,2263.73 2216.54,2275.59 2216.54,2637.8 2232.28,2653.54 2232.28,2669.29 2232.28,3015.75 v1(2251.97,3035.43)
  MidLayer2 w5: v1(2440.94,3271.65) 2472.44,3303.15 2472.44,3385.83 2484.25,3397.64 2484.25,3417.32 2519.69,3452.76 2570.87,3452.76 2606.3,3488.19 2606.3,3507.87 2598.43,3515.75 2598.43,3543.31 2657.48,3602.36 2657.48,3673.23 2645.67,3685.04 2645.67,3704.72 2649.61,3708.66 v2(2649.61,3826.77)
  MidLayer3 w5: v1(2251.97,3035.43) 2232.28,3055.12 2232.28,3165.35 2279.53,3212.6 2381.89,3212.6 v1(2440.94,3271.65)
BUS_D12: U1.H23 U1_CM.F5 U2_CM.48 U4_CM.35 | length 4255.5
  Top Layer w5: v2(1519.68,3826.77) U2_CM.48@1519.69,3901.57 ; v2(2476.38,3692.91) 2555.12,3771.65 v2(2555.12,3850.39) U4_CM.35@2555.12,3901.57
  Top Layer w7.87: U1.H23@1897.64,1692.91 v1(1917.33,1712.6) ; U1_CM.F5@2311.02,3016.73 v1(2330.71,3035.43)
  MidLayer1 w5: v2(1519.68,3826.77) 1586.6,3759.84 2342.52,3759.84 2377.95,3724.41 2440.94,3724.41 2472.44,3692.91 v2(2476.38,3692.91) ; v1(1917.33,1712.6) 1937.01,1732.28 2078.74,1732.28 2090.55,1732.28 2145.67,1732.28 2279.53,1866.14 2279.53,2236.22 2267.72,2248.03 2267.72,2263.78 2279.53,2275.59 2279.53,2637.79 2311.02,2669.29 2311.02,3015.75 v1(2330.71,3035.43) 2330.22,3035.93 v1@2326.78,3039.37
  MidLayer2 w5: v1(2401.57,3271.65) 2448.82,3318.9 2448.82,3385.83 2440.94,3393.7 2440.94,3413.39 2468.5,3440.94 2488.19,3440.94 2513.78,3466.54 2541.34,3466.54 2547.24,3472.44 2566.93,3492.13 2566.93,3507.87 2574.8,3515.75 2574.8,3531.5 2555.12,3551.18 2551.18,3555.12 2551.18,3677.17 2559.05,3685.04 2559.05,3704.72 2555.12,3708.66 v2(2555.12,3850.39)
  MidLayer3 w5: v1(2330.71,3035.43) 2311.02,3015.75 2200.79,3015.75 2192.91,3023.62 2192.91,3161.42 2255.91,3224.41 2354.33,3224.41 v1(2401.57,3271.65)
BUS_D13: U1.A23 U1_CM.G6 U2_CM.50 U4_CM.36 | length 3776.1
  Top Layer w5: v2(1456.69,3826.77) U2_CM.50@1456.69,3901.57 ; U1.A23@1897.64,1968.5 1897.64,2031.5 1897.64,2043.31 1897.64,2070.87 1996.06,2169.29 1996.06,2259.84 1984.25,2271.65 1984.25,2314.96 2192.91,2523.62 2192.91,2838.58 ; 2192.91,2822.83 2192.91,2929.14 2220.47,2956.69 v1(2251.97,2956.69) ; v1@2251.97,2957.68 U1_CM.G6@2271.65,2977.36 ; v2(2444.88,3669.29) 2444.88,3692.91 2523.62,3771.65 v2(2523.62,3826.77) U4_CM.36@2523.62,3901.57
  MidLayer1 w5: v2(1456.69,3826.77) 1535.43,3748.03 2338.58,3748.03 2374.02,3712.6 2425.2,3712.6 2444.88,3692.91 v2(2444.88,3669.29)
  MidLayer2 w5: v1(2362.2,3271.65) 2409.45,3318.9 2409.45,3385.83 2417.32,3393.7 2417.32,3417.32 2433.07,3433.07 2440.94,3433.07 2464.57,3456.69 2484.25,3456.69 2507.87,3480.32 2523.62,3480.32 2535.43,3480.31 2543.31,3488.19 2543.31,3507.87 2531.5,3519.69 2531.5,3673.23 2519.68,3685.04 2519.68,3704.72 2523.62,3708.66 v2(2523.62,3826.77)
  MidLayer3 w5: v1(2251.97,2956.69) 2212.6,2956.69 2181.1,2988.19 2181.1,3169.29 2248.03,3236.22 2326.77,3236.22 v1(2362.2,3271.65)
BUS_D14: U1.G23 U1_CM.F6 U2_CM.51 U4_CM.37 | length 4174.5
  Top Layer w5: v2(1425.2,3850.39) U2_CM.51@1425.2,3901.57 ; v2(2413.38,3692.91) 2492.13,3771.65 v2(2492.13,3850.39) U4_CM.37@2492.13,3901.57
  Top Layer w7.87: U1.G23@1897.64,1732.28 v1(1917.32,1751.97) ; v1@2290.85,2957.19 U1_CM.F6@2311.02,2977.36
  MidLayer1 w5: v2(1425.2,3850.39) 1425.2,3830.71 1519.69,3736.22 2334.65,3736.22 2377.95,3692.91 v2(2413.38,3692.91) ; v1(1917.32,1751.97) 1937.01,1771.65 2078.74,1771.65 2090.55,1771.65 2098.43,1771.65 2267.72,1940.94 2267.72,2220.47 2244.09,2244.09 2244.09,2263.78 2232.28,2275.59 2232.28,2610.24 2275.59,2653.54 2275.59,2673.23 2263.78,2685.04 2263.78,2696.85 2271.65,2704.72 2271.65,2937.01 v1(2291.34,2956.69) v1@2291.34,2957.68
  MidLayer2 w5: v1(2326.77,3271.65) 2385.83,3330.71 2385.83,3385.83 2377.95,3393.7 2377.95,3417.32 2405.51,3444.88 2433.07,3444.88 2456.69,3468.5 2480.31,3468.5 2503.94,3492.13 2503.94,3507.87 2511.81,3515.75 2511.81,3531.5 2492.13,3551.18 2488.19,3555.12 2488.19,3677.17 2496.06,3685.04 2496.06,3704.72 2492.13,3708.66 v2(2492.13,3850.39)
  MidLayer3 w5: v1(2291.34,2956.69) 2271.66,2937.01 2216.54,2937.01 2141.73,3011.81 2141.73,3145.67 2244.09,3248.03 2303.15,3248.03 v1(2326.77,3271.65)
BUS_D15: U1.A25 U1_CM.G7 U2_CM.53 U4_CM.38 | length 3779.7
  Top Layer w5: v2(1362.2,3850.39) U2_CM.53@1362.2,3901.57 ; U1.A25@1976.38,1968.5 1976.38,2031.5 1976.38,2043.31 1976.38,2051.18 2003.94,2078.74 2003.94,2106.3 2059.06,2161.42 2059.06,2259.84 2047.24,2271.65 2047.24,2287.4 2275.59,2515.75 2275.59,2673.23 2251.97,2696.85 2251.97,2819.14 ; 2251.97,2814.96 v1(2251.97,2917.32) v1@2251.97,2918.31 ; v2(2381.89,3669.29) 2381.89,3696.85 2460.63,3775.59 v2(2460.63,3826.77) U4_CM.38@2460.63,3901.57
  Top Layer w7.87: v1@2251.97,2918.31 U1_CM.G7@2271.65,2937.99
  MidLayer1 w5: v2(1362.2,3850.39) 1362.2,3830.71 1468.5,3724.41 2326.77,3724.41 v2(2381.89,3669.29)
  MidLayer2 w5: v1(2291.34,3271.65) 2346.46,3326.77 2346.46,3385.83 2357.28,3396.65 2357.28,3416.34 2397.64,3456.69 2425.2,3456.69 2448.82,3480.32 2472.44,3480.32 2480.31,3488.19 2480.31,3507.87 2468.5,3519.69 2468.5,3673.23 2456.69,3685.04 2456.69,3704.72 2460.63,3708.66 v2(2460.63,3826.77)
  MidLayer3 w5: v1(2251.97,2917.32) 2232.28,2897.64 2192.91,2897.64 2129.92,2960.63 2129.92,3149.61 2251.97,3271.65 v1(2291.34,3271.65)
BUS_D16: U1.C20 U3_CM.2 U5_CM.7 | length 3588.2
  Top Layer w7.87: U1.C20@1779.53,1889.76 v1(1799.21,1909.45)
  MidLayer3 w5: v1(1799.21,1909.45) 1818.9,1929.13 1818.9,2030.18 1818.9,2043.31 1818.9,2110.24 1905.51,2196.85 1988.19,2196.85 2015.75,2224.41 2015.75,2263.78 2027.56,2275.59 2027.56,2295.27 2066.93,2334.64 2066.93,2661.42 2153.54,2748.03 2488.19,2748.03 2807.09,3066.93 2807.09,3141.73 2807.09,3229.33 2807.09,3377.95 2807.09,3397.64 2838.58,3429.13 v2(2838.58,3500) ; v2(2051.18,3665.35) 2051.18,3578.74 2098.43,3531.5 2098.43,3519.68 2118.11,3500 v2(2118.11,3405.51)
  Bottom Layer w5: v2(2051.18,3665.35) 2086.61,3629.92 2763.78,3629.92 2826.77,3566.93 2826.77,3529.53 2838.58,3517.72 v2(2838.58,3500) 2818.9,3500 2807.09,3488.19 U5_CM.7@2807.09,3452.76 ; v2(2118.11,3405.51) U3_CM.2@2118.11,3452.76
BUS_D17: U1.G18 U3_CM.4 U5_CM.8 | length 3808.8
  Top Layer w7.87: U1.G18@1700.79,1732.28 v1(1720.47,1751.97)
  MidLayer3 w5: v1(1720.47,1751.97) 1740.16,1771.66 1740.16,2031.5 1740.16,2043.31 1740.16,2066.93 1893.7,2220.47 1921.26,2220.47 1952.76,2251.97 1952.76,2263.78 1964.57,2275.59 1964.57,2299.21 1952.76,2311.02 1952.76,2677.17 2047.24,2771.65 2480.31,2771.65 2775.59,3066.93 2775.59,3397.64 2807.09,3429.13 v2(2807.09,3523.62) ; v2(2019.68,3665.35) 2019.68,3590.55 2074.8,3535.43 2074.8,3519.68 2055.12,3500 v2(2055.12,3405.51)
  Bottom Layer w5: v2(2019.68,3665.35) 2066.93,3618.11 2696.85,3618.11 2751.97,3562.99 2751.97,3543.31 2771.65,3523.62 v2(2807.09,3523.62) 2807.09,3503.94 2775.59,3472.44 U5_CM.8@2775.59,3452.76 ; v2(2055.12,3405.51) U3_CM.4@2055.12,3452.76
BUS_D18: U1.G16 U3_CM.5 U5_CM.9 | length 3814.1
  Top Layer w7.87: U1.G16@1622.05,1732.28 v1(1641.73,1751.97)
  MidLayer3 w5: v1(1641.73,1751.97) 1661.42,1771.66 1661.42,2031.5 1661.42,2043.31 1661.42,2078.74 1696.85,2114.17 1755.91,2114.17 1889.76,2248.03 1889.76,2263.78 1901.57,2275.59 1901.57,2299.21 1929.13,2326.77 1929.13,2685.04 2039.37,2795.28 2472.44,2795.28 2744.09,3066.93 2744.09,3468.5 v2(2775.59,3500) ; v2(1988.19,3665.35) 1988.19,3566.93 2042.85,3512.27 2043.31,3512.27 2043.31,3496.06 2023.62,3476.38 v2(2023.62,3405.51)
  Bottom Layer w5: v2(1988.19,3665.35) 2047.24,3606.3 2688.98,3606.3 2732.28,3562.99 2732.28,3539.37 2724.41,3531.5 2724.41,3515.75 2740.16,3500 2744.09,3500 ; v2(2023.62,3405.51) U3_CM.5@2023.62,3452.76 ; U5_CM.9@2744.09,3452.76 2744.09,3500 ; v2(2775.59,3500) 2744.09,3500
BUS_D19: U1.G15 U3_CM.7 U5_CM.10 | length 3792.4
  Top Layer w7.87: U1.G15@1582.68,1732.28 v1(1602.36,1751.97)
  MidLayer3 w5: v1(1602.36,1751.97) 1582.68,1771.66 1582.68,2031.5 1582.68,2043.31 1582.68,2066.93 1716.54,2200.79 1807.09,2200.79 1826.77,2220.47 1826.77,2263.78 1838.58,2275.59 1838.58,2299.21 1858.27,2318.9 1858.27,2673.23 1874.02,2688.98 1874.02,2704.72 1988.19,2818.9 2464.57,2818.9 2712.6,3066.93 ; v2(1956.69,3665.35) 1956.69,3535.43 1980.31,3511.81 1980.31,3496.06 1960.63,3476.38 v2(1960.63,3405.51) ; 2712.46,3066.93 2712.57,3401.57 v2(2712.6,3500)
  Bottom Layer w5: v2(1956.69,3665.35) 2027.56,3594.49 2637.8,3594.49 2712.6,3519.69 v2(2712.6,3500) U5_CM.10@2712.6,3452.76 ; v2(1960.63,3405.51) U3_CM.7@1960.63,3452.76
BUS_D20: U1.G14 U3_CM.8 U5_CM.13 | length 3816.7
  Top Layer w7.87: U1.G14@1543.31,1732.28 v1(1562.99,1751.97)
  MidLayer3 w5: v1(1562.99,1751.97) 1543.31,1771.65 1543.31,2031.5 1543.31,2043.31 1543.31,2062.99 1692.91,2212.6 1771.65,2212.6 1803.15,2244.09 1803.15,2263.78 1791.34,2275.59 1791.34,2295.27 1838.58,2342.52 1838.58,2669.29 1826.77,2681.1 1826.77,2696.85 2027.56,2897.64 2106.3,2897.64 2129.92,2874.02 2314.96,2874.02 2342.52,2901.57 2342.52,2956.69 2362.2,2976.38 2468.5,2976.38 2507.87,3015.75 2539.37,3015.75 2590.55,3066.93 2590.55,3370.08 2570.87,3389.76 2570.87,3421.26 2618.11,3468.5 v2(2618.11,3523.62) ; v2(1925.2,3665.35) 1925.2,3555.12 1909.45,3539.37 1909.45,3519.68 1929.13,3500 v2(1929.13,3377.95)
  Bottom Layer w5: v2(1925.2,3665.35) 2007.87,3582.68 2559.06,3582.68 v2(2618.11,3523.62) 2618.11,3500 U5_CM.13@2618.11,3452.76 ; v2(1929.13,3377.95) U3_CM.8@1929.13,3452.76
BUS_D21: U1.F10 U3_CM.10 U5_CM.14 | length 3722.4
  Top Layer w7.87: v1(1366.14,1791.34) U1.F10@1385.83,1771.65
  MidLayer3 w5: v1(1366.14,1791.34) 1385.83,1811.02 1385.83,2031.49 1385.83,2043.31 1385.83,2110.24 1511.81,2236.22 1692.91,2236.22 1700.79,2244.09 1700.79,2263.78 1712.6,2275.59 1712.6,2291.34 1771.65,2350.39 1771.65,2673.23 1751.97,2692.91 1751.97,2708.66 1992.13,2948.82 2078.74,2948.82 2118.11,2988.19 2118.11,3153.54 2145.67,3181.1 2263.78,3299.21 2523.62,3299.21 2566.93,3342.52 2566.93,3362.2 2547.24,3381.89 2547.24,3429.13 2586.61,3468.5 v2(2586.61,3500) ; v2(1866.14,3405.51) 1866.14,3500 1885.83,3519.68 1885.83,3535.43 1893.7,3543.31 v2(1893.7,3665.35)
  Bottom Layer w5: v2(1866.14,3405.51) U3_CM.10@1866.14,3452.76 ; v2(1893.7,3665.35) 1988.19,3570.87 2535.43,3570.87 2586.61,3519.69 v2(2586.61,3500) U5_CM.14@2586.61,3452.76
BUS_D22: U1.G9 U3_CM.11 U5_CM.15 | length 3682.4
  Top Layer w7.87: v1(1326.77,1751.97) U1.G9@1346.46,1732.28
  MidLayer3 w5: v1(1326.77,1751.97) 1346.46,1771.65 1346.46,2031.5 1346.46,2043.31 1346.46,2098.43 1551.18,2303.15 1704.72,2303.15 1728.35,2326.77 1728.35,2669.29 1740.16,2681.1 1740.16,2716.54 1984.25,2960.63 2070.87,2960.63 2106.3,2996.06 2106.3,3200.79 2216.54,3311.02 2496.06,3311.02 v1(2543.31,3358.27) ; v2(1834.65,3405.51) 1834.65,3476.38 1854.33,3496.06 1854.33,3511.81 1846.46,3519.69 1846.46,3566.93 1862.2,3582.68 v2(1862.2,3665.35)
  Bottom Layer w5: v2(1834.65,3405.51) U3_CM.11@1834.65,3452.76 ; v2(1862.2,3665.35) 1968.5,3559.06 2507.87,3559.06 2535.43,3531.5 2535.43,3515.75 2555.12,3496.06 U5_CM.15@2555.12,3452.76 2555.12,3417.32 2555.12,3393.7 2543.31,3381.89 v1(2543.31,3358.27)
BUS_D23: U1.G8 U3_CM.13 U5_CM.16 | length 3762.3
  Top Layer w7.87: v1(1287.4,1751.97) U1.G8@1307.09,1732.28
  MidLayer3 w5: v1(1287.4,1751.97) 1307.09,1771.65 1307.09,2029.37 1307.09,2043.31 1307.09,2098.43 1366.14,2157.48 1366.14,2181.1 1500,2314.96 1641.73,2314.96 1700.79,2374.02 1700.79,2700.79 1812.99,2812.99 1972.44,2972.44 2062.99,2972.44 2094.49,3003.94 2094.49,3204.72 2212.6,3322.83 2480.31,3322.83 2527.56,3370.08 2527.56,3381.89 ; v2(1771.65,3377.95) 1771.65,3429.13 1811.02,3468.5 1811.02,3507.87 1830.71,3527.56 v2(1830.71,3665.35) ; 2527.56,3369.83 v2(2527.56,3401.57)
  Bottom Layer w5: v2(1771.65,3377.95) U3_CM.13@1771.65,3452.76 ; v2(1830.71,3665.35) 1948.82,3547.24 2496.06,3547.24 2511.81,3531.5 2511.81,3515.75 2503.94,3507.87 2503.94,3492.13 2523.62,3472.44 U5_CM.16@2523.62,3452.76 2527.56,3448.82 v2(2527.56,3401.57)
BUS_D24: U1.F9 U3_CM.42 U5_CM.29 | length 4190.7
  Top Layer w7.87: v1(1326.77,1791.34) U1.F9@1346.46,1771.65
  MidLayer2 w5: v1(1326.77,1791.34) 1307.09,1811.03 1307.09,2031.5 1307.09,2043.31 1307.09,2090.55 1295.28,2102.36 1295.28,2236.22 1397.64,2338.58 1606.3,2338.58 1657.48,2389.76 1657.48,2649.61 1677.17,2669.29 1677.17,2708.66 1728.35,2759.84 2011.81,2759.84 2043.31,2791.34 2043.31,2968.5 2106.3,3031.5 2106.3,3236.22 2354.33,3484.25 2354.33,3507.87 2346.46,3515.75 2346.46,3696.85 2377.95,3728.35 2377.95,3834.65 2444.88,3901.57 2472.77,3901.57 v2(2523.62,3952.42) ; v2(1771.65,3948.82) 1771.65,3850.39 1830.71,3791.34 v2(1830.71,3704.72)
  Bottom Layer w5: U3_CM.42@1771.65,3901.57 v2(1771.65,3948.82) ; v2(1830.71,3704.72) 1933.07,3807.09 2476.38,3807.09 2523.62,3854.33 U5_CM.29@2523.62,3901.57 v2(2523.62,3952.42)
BUS_D25: U1.G6 U3_CM.44 U5_CM.30 | length 4343.6
  Top Layer w7.87: v1(1208.66,1751.97) U1.G6@1228.35,1732.28
  MidLayer2 w5: v2(1834.65,3948.82) 1834.65,3854.33 1862.2,3826.77 v2(1862.2,3704.72)
  MidLayer3 w5: v1(1208.66,1751.97) 1188.98,1771.65 1161.42,1771.65 1149.61,1783.46 1149.61,2031.5 1149.61,2043.31 1149.61,2055.12 1165.35,2070.87 1165.35,2106.3 1397.64,2338.58 1633.86,2338.58 1677.17,2381.89 1677.17,2724.41 2003.94,3051.18 2031.5,3051.18 2070.87,3090.55 2070.87,3212.6 2204.72,3346.46 2440.94,3346.46 2472.44,3377.95 2472.44,3385.83 2484.25,3397.64 2484.25,3417.32 2490.16,3423.23 2543.31,3476.38 2543.31,3507.87 2535.43,3515.75 2535.43,3661.42 2562.99,3688.98 2562.99,3830.71 2574.8,3842.52 2574.8,3858.27 2555.12,3877.95 v2(2555.12,3952.76)
  Bottom Layer w5: U3_CM.44@1834.65,3901.57 v2(1834.65,3948.82) ; v2(1862.2,3704.72) 1952.76,3795.28 2519.68,3795.28 2543.31,3818.9 2543.31,3834.65 2535.43,3842.52 2535.43,3862.2 2555.12,3881.89 U5_CM.30@2555.12,3901.57 v2(2555.12,3952.76)
BUS_D26: U1.F6 U3_CM.45 U5_CM.31 | length 4150.5
  Top Layer w7.87: v1(1208.66,1791.34) U1.F6@1228.35,1771.65 v1(1208.66,1791.34)
  MidLayer2 w5: v2(1866.14,3948.82) 1866.14,3877.95 1885.83,3858.27 1885.83,3842.52 1877.95,3834.65 1877.95,3818.9 1893.7,3803.15 v2(1893.7,3704.72)
  MidLayer3 w5: v1(1208.66,1791.34) 1188.98,1811.02 1188.98,2031.5 1188.98,2043.31 1188.98,2094.49 1299.21,2204.72 1326.77,2204.72 1448.82,2326.77 1637.8,2326.77 1688.98,2377.95 1688.98,2708.66 1964.57,2984.25 2051.18,2984.25 2082.68,3015.75 2082.68,3209.65 2089.57,3216.54 2207.68,3334.65 2476.38,3334.65 2511.81,3370.08 2511.81,3389.76 2507.87,3393.7 2507.87,3417.32 2566.93,3476.38 2566.93,3507.87 2574.8,3515.75 2574.8,3590.55 2590.55,3606.3 2590.55,3677.17 2582.68,3685.04 2582.68,3704.72 2586.61,3708.66 v2(2586.61,3826.77)
  Bottom Layer w5: U3_CM.45@1866.14,3901.57 v2(1866.14,3948.82) ; v2(1893.7,3704.72) 1972.44,3783.46 2543.31,3783.46 v2(2586.61,3826.77) U5_CM.31@2586.61,3901.57
BUS_D27: U1.G12 U3_CM.47 U5_CM.32 | length 4240.1
  Top Layer w7.87: v1(1444.88,1751.97) U1.G12@1464.57,1732.28
  MidLayer2 w5: v2(1925.2,3704.72) 1925.2,3818.9 1948.82,3842.52 1948.82,3858.27 1929.13,3877.95 v2(1929.13,3972.44)
  MidLayer3 w5: v1(1444.88,1751.97) 1464.57,1771.66 1464.57,1836.62 1464.57,1958.66 1480.31,1974.41 1480.32,2031.5 1480.31,2043.31 1480.31,2185.04 1519.68,2224.41 1720.47,2224.41 1740.16,2244.09 ; 1736.22,2240.16 1740.16,2244.09 ; v2(2618.11,3850.39) 2618.11,3708.66 2622.05,3704.72 2622.05,3685.04 2614.17,3677.17 2614.17,3551.18 2598.43,3535.43 2598.43,3515.75 2606.3,3507.87 2606.3,3472.44 2559.06,3425.2 2559.06,3385.83 2578.74,3366.14 2578.74,3149.61 2523.62,3094.49 2480.31,3094.49 2468.5,3082.68 2468.5,3027.56 2456.69,3015.75 2377.95,3015.75 2318.9,2956.69 2318.9,2905.51 2299.21,2885.83 2137.8,2885.83 2114.17,2909.45 1972.44,2909.45 1803.15,2740.16 1803.15,2681.1 1783.46,2661.42 1783.46,2342.52 1728.35,2287.4 1728.35,2275.59 1740.16,2263.78 1740.16,2244.09
  Bottom Layer w5: v2(1925.2,3704.72) 1992.13,3771.65 2559.05,3771.65 2618.11,3830.71 v2(2618.11,3850.39) U5_CM.32@2618.11,3901.57 ; U3_CM.47@1929.13,3901.57 v2(1929.13,3972.44)
BUS_D28: U1.E16 U3_CM.48 U5_CM.35 | length 4272.3
  Top Layer w7.87: U1.E16@1622.05,1811.02 v1(1641.73,1830.71)
  MidLayer2 w5: v2(1956.69,3704.72) 1956.69,3795.28 1980.31,3818.9 1980.31,3834.65 1960.63,3854.33 v2(1960.63,3972.44)
  MidLayer3 w5: v1(1641.73,1830.71) 1622.05,1850.39 1622.05,2031.5 1622.05,2043.31 1622.05,2070.87 1740.16,2188.98 1814.96,2188.98 1866.14,2240.16 1866.14,2263.78 1854.33,2275.59 1854.33,2287.4 1901.57,2334.65 1901.57,2669.29 1885.83,2685.04 1885.83,2696.85 1996.06,2807.09 2468.5,2807.09 2732.28,3070.87 2732.28,3507.87 2724.41,3515.75 2724.41,3531.49 2732.28,3539.37 2732.28,3559.06 2716.54,3574.8 2716.54,3677.17 2708.66,3685.04 2708.66,3704.72 2712.6,3708.66 2712.6,3799.21 2732.28,3818.9 2732.28,3834.65 2712.6,3854.33 v2(2712.6,3952.76)
  Bottom Layer w5: v2(1956.69,3704.72) 2011.81,3759.84 2618.11,3759.84 2712.6,3854.33 U5_CM.35@2712.6,3901.57 v2(2712.6,3952.76) ; v2@1956.69,3972.44 v2(1960.63,3972.44) U3_CM.48@1960.63,3901.57
BUS_D29: U1.G17 U3_CM.50 U5_CM.36 | length 4345.4
  Top Layer w7.87: U1.G17@1661.42,1732.28 v1(1681.1,1751.97)
  MidLayer2 w5: v2(1988.19,3704.72) 1988.19,3763.78 2043.31,3818.9 2043.31,3834.65 2023.62,3854.33 v2(2023.62,3948.82)
  MidLayer3 w5: v1(1681.1,1751.97) 1700.79,1771.66 1700.79,2031.5 1700.79,2043.31 1700.79,2078.74 1724.41,2102.36 1759.84,2102.36 1889.76,2232.28 1917.32,2232.28 1929.13,2244.09 1929.13,2263.78 1917.32,2275.59 1917.32,2287.4 1940.94,2311.02 1940.94,2681.1 2043.31,2783.46 2476.38,2783.46 2763.78,3070.87 2763.78,3401.57 2795.28,3433.07 2795.28,3507.87 2779.53,3523.62 2771.65,3523.62 2751.97,3543.31 2751.97,3559.06 2740.16,3570.87 2740.16,3677.17 2748.03,3685.04 2748.03,3704.72 2744.09,3708.66 2744.09,3822.83 2763.78,3842.52 2763.78,3858.27 2744.09,3877.95 v2(2744.09,3976.38)
  Bottom Layer w5: v2(1988.19,3704.72) 2031.5,3748.03 2661.42,3748.03 2732.28,3818.9 2732.28,3834.65 2724.41,3842.52 2724.41,3862.2 2744.09,3881.89 U5_CM.36@2744.09,3901.57 v2(2744.09,3976.38) ; U3_CM.50@2023.62,3901.57 v2(2023.62,3948.82)
BUS_D30: U1.E19 U3_CM.51 U5_CM.37 | length 4148.1
  Top Layer w7.87: U1.E19@1740.16,1811.02 v1(1759.84,1830.71)
  MidLayer2 w5: v2(2019.68,3704.72) 2019.68,3767.72 2066.93,3814.96 2066.93,3834.65 2074.8,3842.52 2074.8,3858.27 2055.12,3877.95 v2(2055.12,3948.82)
  MidLayer3 w5: v1(1759.84,1830.71) 1779.53,1850.39 1779.53,1962.6 1803.15,1986.22 1803.15,2031.5 1803.15,2043.31 1803.15,2114.17 1897.64,2208.66 1956.69,2208.66 1992.12,2244.09 1992.12,2263.78 1980.31,2275.59 1980.31,2295.27 2055.12,2370.08 2055.12,2673.23 2047.24,2681.1 2047.24,2696.85 2110.23,2759.84 2484.25,2759.84 2787.4,3062.99 2787.4,3393.7 2818.9,3425.2 2818.9,3507.87 2826.77,3515.75 2826.77,3566.93 2779.53,3614.17 2779.53,3677.17 2771.65,3685.04 2771.65,3704.72 2775.59,3708.66 2775.59,3795.28 2795.28,3814.96 2795.28,3834.65 2775.59,3854.33 v2(2775.59,3952.76)
  Bottom Layer w5: v2(2019.68,3704.72) 2051.18,3736.22 2669.29,3736.22 2755.9,3822.83 2755.9,3834.65 2775.59,3854.33 U5_CM.37@2775.59,3901.57 v2(2775.59,3952.76) ; U3_CM.51@2055.12,3901.57 v2(2055.12,3948.82)
BUS_D31: U1.D22 U3_CM.53 U5_CM.38 | length 4026.1
  Top Layer w7.87: U1.D22@1858.27,1850.39 v1(1877.96,1870.08)
  MidLayer2 w5: v2(2051.18,3704.72) 2051.18,3755.91 2137.8,3842.52 2137.8,3862.2 2118.11,3881.89 v2(2118.11,3948.82)
  MidLayer3 w5: v1(1877.96,1870.08) 1897.64,1889.76 1897.64,2031.5 1897.64,2043.31 1897.64,2070.87 1929.13,2102.36 1929.13,2122.05 2055.12,2248.03 2055.12,2263.78 2043.3,2275.59 2043.3,2291.34 2078.74,2326.77 2078.74,2610.24 2204.72,2736.22 2492.12,2736.22 2818.9,3062.99 2818.9,3393.7 2858.27,3433.07 2858.27,3507.87 2850.39,3515.75 2850.39,3531.5 2866.14,3547.24 2866.14,3562.99 2803.15,3625.98 2803.15,3677.17 2811.02,3685.04 2811.02,3704.72 2807.09,3708.66 2807.09,3822.83 2826.77,3842.52 2826.77,3858.27 2807.09,3877.95 v2(2807.09,3952.76)
  Bottom Layer w5: v2(2051.18,3704.72) 2070.87,3724.41 2704.72,3724.41 2795.28,3814.96 2795.28,3834.65 2787.4,3842.52 2787.4,3862.2 2807.09,3881.89 U5_CM.38@2807.09,3901.57 v2(2807.09,3952.76) ; U3_CM.53@2118.11,3901.57 v2(2118.11,3948.82)
BUS_FLASH_NBUSY: U1.H25 U1_CM.A4 | length 1746.8
  Top Layer w5: U1.H25@1976.38,1692.91 1996.06,1712.6 2078.74,1712.6 2090.55,1712.6 2173.23,1712.6 2287.4,1826.77 2287.4,2011.81 2346.46,2070.87 2433.07,2157.48 2433.07,2263.78 2425.2,2271.65 2425.2,2291.34 2452.76,2318.9 2452.76,2606.3 2511.81,2665.35 2511.81,2818.9 2570.87,2877.95 2570.87,2996.07 v1(2527.56,3035.43)
  Top Layer w7.87: U1_CM.A4@2507.87,3056.1 v1(2527.56,3035.43)
BUS_FLASH_NCS: U1.A19 U1_CM.F2 | length 1632.8
  Top Layer w5: U1.A19@1740.16,1968.5 1740.16,1984.25 1724.41,2000 1724.41,2031.5 1724.41,2043.31 1724.41,2169.29 1803.15,2248.03 1803.15,2263.78 1795.27,2271.65 1795.27,2287.4 2011.81,2503.94 2011.81,2669.29 2027.56,2685.04 2027.56,2696.85 2114.17,2783.46 2114.17,2956.69 2129.92,2972.44 2129.92,3122.05 2212.6,3204.72 2271.65,3204.72 2291.34,3185.04 2291.34,3161.42 2299.21,3153.54 v1(2330.71,3153.54) ; U1_CM.F2@2310.03,3134.85 U1_CM.F2@2311.02,3134.84
  Top Layer w7.87: U1_CM.F2@2311.02,3134.84 v1(2330.71,3153.54)
BUS_FLASH_NRESET: U1.M22 U1_CM.B5 | length 2096
  Top Layer w7.87: U1.M22@1858.27,1535.43 v1(1877.96,1555.12) ; v1(2448.82,3035.43) U1_CM.B5@2468.5,3016.73
  MidLayer1 w5: v1(1877.96,1555.12) 1897.64,1574.8 2078.74,1574.8 2090.55,1574.8 2181.1,1574.8 2374.02,1767.72 2374.02,2141.73 2456.69,2224.41 2496.06,2224.41 2519.68,2248.03 2519.68,2263.78 2543.31,2287.4 2543.31,2740.16 2559.06,2755.91 2559.06,3000 2543.31,3015.75 2507.87,3015.75 2488.19,3035.43 v1(2448.82,3035.43)
BUS_NBE0: RN33.6 RN34.7 U1.F11 U2_CM.15 U4_CM.39 | length 4268.9
  Top Layer w5: U2_CM.15@1771.65,3452.75 v2(1771.65,3503.93) ; v2(2429.13,3850.39) U4_CM.39@2429.13,3901.57
  Top Layer w7.87: v1(1405.51,1791.34) U1.F11@1425.2,1771.65
  MidLayer2 w5: v1(1405.51,1791.34) 1385.83,1811.02 1385.83,2031.49 1385.83,2043.31 1385.83,2200.79 1425.2,2240.16 1425.2,2259.84 1413.38,2271.65 1413.38,2283.46 1444.88,2314.96 1614.17,2314.96 1681.1,2381.89 1681.1,2641.73 1700.79,2661.42 1700.79,2700.79 1736.22,2736.22 2023.62,2736.22 2102.36,2814.96 2102.36,2988.19 2129.92,3015.75 2129.92,3228.35 2370.08,3468.5 2417.32,3468.5 2440.94,3492.13 2440.94,3507.87 2448.82,3515.75 2448.82,3531.5 2425.2,3555.12 2425.2,3677.17 2433.07,3685.04 2433.07,3704.72 2429.13,3708.66 v2(2429.13,3850.39) ; v1(1742.14,3311.02) 1742.14,3376 1771.65,3405.51 v2(1771.65,3503.93)
  MidLayer3 w5: v2(1771.65,3503.93) 1771.65,3657.49 1748.03,3681.1 1748.03,3767.72 1862.2,3881.89 2397.64,3881.89 v2(2429.13,3850.39)
  Bottom Layer w5: RN33.6@1688.58,3311.02 v1(1742.14,3311.02) RN34.7@1779.53,3311.02 RN34.7@1779.92,3311.02
BUS_NBE1: RN37.5 RN38.8 U1.E10 U2_CM.39 U4_CM.40 | length 3939
  Top Layer w5: U2_CM.39@1803.14,3901.57 v2(1803.14,3850.39) 1803.14,3818.9 1818.89,3803.15 2374.02,3803.15 v2(2397.64,3826.77) U4_CM.40@2397.64,3901.57
  Top Layer w7.87: v1(1366.14,1830.71) U1.E10@1385.83,1811.02
  MidLayer2 w5: v1(1366.14,1830.71) 1346.46,1850.39 1346.46,2031.5 1346.46,2043.31 1346.46,2220.47 1397.64,2271.65 1397.64,2283.47 1440.94,2326.77 1610.24,2326.77 1669.29,2385.83 1669.29,2645.67 1688.98,2665.35 1688.98,2704.72 1732.28,2748.03 2015.75,2748.03 2090.55,2822.83 2090.55,2996.06 2118.11,3023.62 2118.11,3232.28 2366.14,3480.32 2409.45,3480.32 2417.32,3488.19 2417.32,3507.87 2405.51,3519.68 2405.51,3673.23 2393.7,3685.04 2393.7,3704.72 2397.64,3708.66 v2(2397.64,3826.77)
  MidLayer3 w5: v1(1618.11,4055.11) 1653.55,4055.11 1708.66,4000 1708.66,3944.88 v2@1803.15,3850.39
  Bottom Layer w5: RN37.5@1586.22,4055.11 v1(1618.11,4055.11) RN38.8@1676.19,4055.12 RN38.8@1677.17,4055.11
BUS_NBE2: RN33.5 RN34.8 U1.F18 U3_CM.15 U5_CM.39 | length 4936.7
  Top Layer w7.87: U1.F18@1700.79,1771.65 v1(1720.47,1791.34)
  MidLayer2 w5: v1(1720.47,1791.34) 1700.79,1811.02 1700.79,1866.14 1700.79,1952.75 1700.79,2031.49 1700.79,2043.31 1700.79,2051.18 1881.89,2232.28 1921.26,2232.28 1992.13,2303.15 1992.13,2673.23 1980.31,2685.04 1980.31,2696.85 1996.06,2712.6 2035.43,2712.6 2125.98,2803.15 2125.98,2976.38 2181.1,3031.5 2181.1,3177.17 2228.35,3224.41 2460.63,3224.41 2476.38,3208.66 2716.54,3208.66 2862.2,3354.33 2862.2,3374.02 2881.89,3393.7 2881.89,3507.87 2889.76,3515.75 2889.76,3531.5 2881.89,3539.37 2881.89,3732.28 2858.27,3755.91 2858.27,3834.65 2838.58,3854.33 v2(2838.58,3976.38)
  MidLayer3 w5: v2(1708.66,3377.95) 1708.66,3409.45 1791.34,3492.13 1791.34,3511.81 1783.46,3519.68 1783.46,3688.98 v2(1799.21,3704.72)
  Bottom Layer w5: U3_CM.15@1708.66,3452.76 v2(1708.66,3377.95) 1708.66,3362.2 1688.98,3342.52 1688.98,3331.1 1688.58,3330.71 RN34.8@1779.53,3330.71 ; v2@1799.21,3696.85 1811.02,3685.04 2078.74,3685.04 2106.3,3712.6 2712.6,3712.6 2818.9,3818.9 2818.9,3834.65 2838.58,3854.33 U5_CM.39@2838.58,3901.57 v2(2838.58,3976.38)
